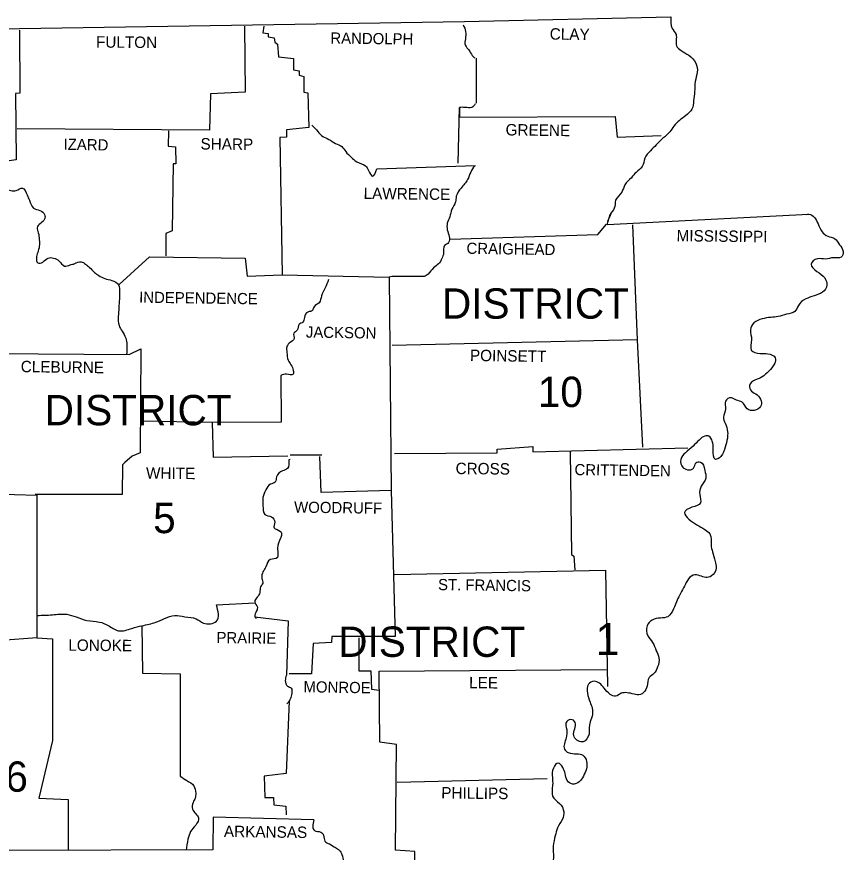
# Model space of a CAD drawing. Extents: x 1370130 to 1380143, y 377636 to 380256.
# Drawn here: x 1379759.2 to 1380085.1, y 379162.8 to 379492.1 of the extents above; entities that cross this region are included whole.
import ezdxf

# ---------------------------------------------------------------- set-up
doc = ezdxf.new("R2010")
doc.units = 0
doc.layers.add('R_Draft', color=7, linetype='Continuous')

msp = doc.modelspace()

# ---------------------------------------------------------------- linework, layer by layer
at = {"layer": 'R_Draft'}
for p, q in [((1379991.99, 379410.22), (1379993.25, 379414.1)), ((1379992.31, 379411.48), (1379993.57, 379414.52)), ((1379866.99, 379319.41), (1379879.47, 379319.41))]:
    msp.add_line(p, q, dxfattribs=at)
for points in [[(1379441.86, 379487.29), (1379611.43, 379487.19), (1379760.24, 379487.5), (1379935.79, 379490.23), (1380017.16, 379492.12)], [(1379760.24, 379486.88), (1379760.45, 379461.92), (1379758.66, 379461.81), (1379758.98, 379435.7), (1379751.64, 379434.65), (1379752.27, 379427.63), (1379754.78, 379424.38), (1379754.57, 379416.09), (1379740.31, 379415.57), (1379739.79, 379402.77), (1379726.78, 379402.35), (1379726.15, 379386.83), (1379726.89, 379385.58), (1379727.2, 379360.83), (1379749.64, 379359.36), (1379749.33, 379304.1), (1379767.16, 379303.57), (1379767.16, 379247.36), (1379753.11, 379246.31), (1379752.06, 379233.94), (1379728.46, 379233.84)], [(1379849.06, 379488.45), (1379849.27, 379462.44), (1379835.64, 379461.71), (1379835.22, 379447.45), (1379759.4, 379447.87)], [(1379856.61, 379488.34), (1379856.3, 379485.83), (1379858.39, 379485.51), (1379858.29, 379484.25), (1379860.7, 379483.73), (1379860.91, 379482.05), (1379862.06, 379481.32), (1379862.38, 379476.28), (1379868.36, 379475.65), (1379868.36, 379471.15), (1379870.56, 379470.83), (1379870.56, 379469.05), (1379872.44, 379468.52), (1379872.34, 379462.44), (1379874.02, 379462.13), (1379874.44, 379448.39), (1379865.52, 379447.55), (1379865.63, 379444.61), (1379862.9, 379444.51), (1379863.85, 379390.4), (1379906.11, 379389.46), (1379906.84, 379305.35), (1379879.26, 379304.62), (1379878.74, 379318.78)], [(1379940.4, 379475.76), (1379940.4, 379458.04)], [(1379933.27, 379434.44), (1379933.79, 379456.36), (1379933.79, 379452.48), (1379995.14, 379452.79), (1379995.98, 379444.61), (1380013.28, 379445.24)], [(1379819.07, 379447.13), (1379818.86, 379441.05), (1379821.79, 379440.84), (1379821.9, 379434.13), (1379820.85, 379434.13), (1379820.43, 379407.7), (1379818.02, 379406.65), (1379818.02, 379397.84)], [(1379901.18, 379432.14), (1379940.08, 379433.5)], [(1379991.99, 379410.22), (1380071.59, 379414.31)], [(1379930.12, 379404.45), (1379988.32, 379406.34), (1379991.78, 379410.32)], [(1380002.06, 379410.11), (1380003.84, 379364.71), (1380005.94, 379322.45)], [(1379799.56, 379386.62), (1379811.52, 379397.43), (1379849.27, 379396.9), (1379850, 379389.88), (1379863.74, 379390.4)], [(1379919.85, 379389.67), (1379907.05, 379389.67), (1379906.11, 379389.46)], [(1380003.84, 379364.71), (1379907.26, 379362.51)], [(1379749.64, 379359.36), (1379803.55, 379359.04), (1379808.16, 379361.25), (1379807.85, 379320.24), (1379804.7, 379318.88), (1379801.87, 379316.47), (1379800.93, 379315.53), (1379800.82, 379303.78), (1379766.53, 379303.78)], [(1379863.32, 379350.76), (1379863.53, 379332.3), (1379836.27, 379332.2), (1379808.27, 379332.72)], [(1379836.27, 379332.2), (1379836.69, 379318.46), (1379866.15, 379318.99)], [(1379908.1, 379320.03), (1379948.58, 379320.24), (1379948.68, 379321.71), (1379962.74, 379322.76), (1379962.74, 379320.56), (1380023.77, 379322.24)], [(1379977.42, 379320.56), (1379977.94, 379280.19), (1379978.89, 379279.56), (1379979.2, 379274.1)], [(1379977.42, 379320.56), (1379977.94, 379280.19), (1379978.89, 379279.56), (1379979.2, 379274.1)], [(1379977.42, 379320.56), (1379977.94, 379280.19), (1379978.89, 379279.56), (1379979.2, 379274.1)], [(1379977.42, 379320.56), (1379977.94, 379280.19), (1379978.89, 379279.56), (1379979.2, 379274.1)], [(1379977.42, 379320.56), (1379977.94, 379280.19), (1379978.89, 379279.56), (1379979.2, 379274.1)], [(1379866.99, 379317.62), (1379866.47, 379317.52)], [(1379906.84, 379305.35), (1379908.41, 379247.89), (1379883.46, 379247.78), (1379883.35, 379245.48), (1379876.12, 379245.06), (1379875.49, 379233.1), (1379866.68, 379233.1)], [(1379908.1, 379272.32), (1379991.37, 379274)], [(1379991.37, 379274), (1379992.2, 379228.07)], [(1379991.37, 379274), (1379992.2, 379228.07)], [(1379991.37, 379274), (1379992.2, 379228.07)], [(1379991.37, 379274), (1379992.2, 379228.07)], [(1379991.37, 379274), (1379992.2, 379228.07)], [(1379991.37, 379274), (1379992.2, 379228.07)], [(1379991.37, 379274), (1379992.2, 379228.07)], [(1379991.37, 379274), (1379992.2, 379228.07)], [(1379837.94, 379260.37), (1379853.15, 379261.1)], [(1379853.15, 379255.65), (1379866.26, 379253.97), (1379865.52, 379232.58)], [(1379808.58, 379252.19), (1379808.79, 379233.42), (1379823.58, 379233.1), (1379823.68, 379192.83)], [(1379767.16, 379247.36), (1379773.24, 379246.94), (1379773.34, 379206.89), (1379767.89, 379184.13), (1379779.53, 379183.61), (1379779.42, 379163.56)], [(1379894.15, 379247.26), (1379894.05, 379234.26), (1379898.87, 379234.26), (1379899.08, 379227.02), (1379902.12, 379226.7)], [(1379908.1, 379141.24), (1379916.28, 379141.76), (1379916.17, 379163.05), (1379908.52, 379163.58), (1379908.94, 379205.21), (1379902.33, 379206.15), (1379902.12, 379234.15), (1379991.57, 379234.78)], [(1379866.68, 379222.51), (1379865.42, 379193.78), (1379856.82, 379192.83), (1379857.03, 379184.34), (1379860.49, 379184.44), (1379860.59, 379181.51), (1379865.31, 379180.98), (1379865.42, 379177.52)], [(1379909.15, 379190.42), (1379968.29, 379191.89)], [(1379876.33, 379175.64), (1379836.69, 379176.68), (1379836.48, 379163.79), (1379756.25, 379163.47)]]:
    msp.add_lwpolyline(points, dxfattribs=at)
for points in [[(1380017.16, 379492.12), (1380017.69, 379487.5), (1380019.16, 379485.09), (1380019.36, 379480.69), (1380021.15, 379478.8), (1380024.19, 379476.91), (1380026.92, 379473.87), (1380027.54, 379470.31), (1380026.71, 379466.64), (1380026.5, 379462.55), (1380026.08, 379458.98), (1380025.45, 379455.73), (1380022.93, 379453.11), (1380020.52, 379451.22), (1380018.32, 379449.02), (1380016.74, 379446.71), (1380014.02, 379444.2), (1380011.29, 379441.57), (1380009.09, 379439.27), (1380006.89, 379436.33), (1380005.84, 379433.08), (1380003.42, 379430.77), (1380001.54, 379428.68), (1379999.02, 379425.84), (1379997.76, 379423.01), (1379995.35, 379419.76), (1379994.83, 379416.62), (1379993.25, 379414.1), (1379993.15, 379413.68)], [(1379935.26, 379488.87), (1379936.2, 379486.25), (1379936.1, 379483.41), (1379936.1, 379480.79), (1379937.46, 379479.01), (1379938.83, 379476.81), (1379939.87, 379475.86)], [(1379939.98, 379457.72), (1379938.62, 379456.36), (1379935.99, 379456.36), (1379933.79, 379456.36)], [(1379875.59, 379449.33), (1379877.9, 379446.92), (1379879.89, 379444.93), (1379882.2, 379443.78), (1379884.92, 379442.2), (1379887.34, 379440.94), (1379888.91, 379438.95), (1379891.11, 379436.75), (1379893.31, 379434.97), (1379896.77, 379433.29), (1379897.93, 379431.51), (1379899.5, 379429.3), (1379901.18, 379432.14)], [(1379939.77, 379433.39), (1379938.2, 379430.88), (1379936.94, 379427.94), (1379934.42, 379424.59), (1379932.53, 379421.33), (1379932.22, 379419.13), (1379930.75, 379416.2), (1379929.91, 379413.26), (1379928.97, 379410.74), (1379928.97, 379408.12), (1379929.7, 379405.5), (1379929.49, 379403.09), (1379927.92, 379401.93), (1379927.5, 379398.89), (1379926.87, 379396.8), (1379925.51, 379394.7), (1379923.52, 379393.13), (1379921.42, 379390.71), (1379919.85, 379389.67)], [(1379754.78, 379424.38), (1379758.98, 379423.64), (1379761.49, 379424.59), (1379763.28, 379421.86), (1379764.22, 379419.76), (1379765.79, 379416.72), (1379768.31, 379415.78), (1379770.2, 379414.1), (1379770.2, 379412.32), (1379768.52, 379410.64), (1379767.26, 379408.96), (1379767.68, 379406.97), (1379768.1, 379404.24), (1379768.1, 379401.62), (1379767.47, 379399.21), (1379766.95, 379397.01), (1379767.47, 379395.12), (1379769.46, 379395.43), (1379771.56, 379397.01), (1379773.76, 379397.01), (1379775.86, 379395.85), (1379778.06, 379393.86), (1379780.27, 379394.28), (1379782.05, 379394.8), (1379784.57, 379395.54), (1379786.35, 379394.59), (1379787.92, 379393.34), (1379789.81, 379391.34), (1379791.59, 379390.08), (1379793.9, 379388.93), (1379796.73, 379388.2), (1379799.35, 379386.41), (1379799.77, 379383.37), (1379799.67, 379380.75), (1379799.46, 379377.5), (1379799.25, 379373.94), (1379799.56, 379370.47), (1379800.72, 379368.17), (1379802.18, 379365.44), (1379802.6, 379362.92), (1379802.5, 379358.94)], [(1380070.44, 379414.2), (1380071.59, 379414.31), (1380075.15, 379410.53), (1380076.73, 379407.39), (1380079.03, 379405.6), (1380081.66, 379404.66), (1380083.65, 379402.25), (1380085.01, 379399.63), (1380084.28, 379397.32), (1380081.34, 379397.11), (1380078.09, 379396.59), (1380074.94, 379396.69), (1380072.43, 379394.59), (1380074.74, 379391.76), (1380077.78, 379389.14), (1380078.62, 379386.31), (1380076.94, 379383.58), (1380073.58, 379382.12), (1380070.33, 379380.86), (1380067.39, 379378.34), (1380066.03, 379375.93), (1380062.78, 379374.88), (1380059.42, 379373.94), (1380056.49, 379373.62), (1380053.13, 379372.99), (1380049.88, 379371.42), (1380048.52, 379368.69), (1380048.94, 379364.81), (1380048.83, 379360.72), (1380052.29, 379359.36), (1380055.33, 379359.25), (1380058.27, 379357.68), (1380057.96, 379355.37), (1380055.75, 379352.44), (1380053.13, 379350.13), (1380050.51, 379348.98), (1380048.1, 379346.78), (1380048.94, 379344.57), (1380051.14, 379343.11), (1380052.71, 379340.69), (1380052.5, 379338.49), (1380049.99, 379336.92), (1380047.26, 379337.55), (1380045.27, 379340.17), (1380042.96, 379341.01), (1380040.97, 379341.95), (1380038.66, 379340.59), (1380038.66, 379337.55), (1380037.82, 379334.3), (1380038.56, 379331.88), (1380039.5, 379328.53), (1380039.39, 379326.01), (1380038.56, 379322.45), (1380036.77, 379318.78), (1380034.68, 379317.62), (1380033.84, 379321.61), (1380033.42, 379324.86), (1380032.16, 379326.75), (1380030.48, 379326.85), (1380028.28, 379325.28), (1380025.87, 379322.87), (1380022.83, 379320.24), (1380021.04, 379317.62), (1380021.99, 379314.37), (1380024.29, 379313.53), (1380026.08, 379314.16), (1380027.02, 379316.26), (1380028.8, 379316.57), (1380030.48, 379313.32)], [(1379882.09, 379388.51), (1379880.83, 379385.26), (1379879.37, 379382.12), (1379878.42, 379379.39), (1379876.43, 379377.82), (1379875.8, 379376.35), (1379874.02, 379375.72), (1379872.65, 379373.62), (1379872.03, 379371.73), (1379870.56, 379370.89), (1379869.82, 379368.59), (1379868.46, 379367.33), (1379868.56, 379365.23), (1379866.99, 379363.76), (1379865.73, 379362.09), (1379865.73, 379359.78), (1379866.26, 379356.74), (1379867.31, 379354.95), (1379868.25, 379352.65), (1379868.15, 379351.18), (1379865.52, 379351.18), (1379863.32, 379350.76)], [(1379866.47, 379317.52), (1379865.94, 379314.06), (1379863.95, 379313.11), (1379861.64, 379310.81), (1379861.12, 379308.71), (1379859.23, 379307.87), (1379857.45, 379305.67), (1379856.3, 379302.63), (1379856.3, 379299.48), (1379857.03, 379295.92), (1379859.65, 379294.97), (1379860.91, 379292.87), (1379860.7, 379290.67), (1379863.22, 379289.2), (1379863.64, 379287.95), (1379863.22, 379286.58), (1379862.06, 379282.7), (1379862.17, 379280.08), (1379861.96, 379278.93), (1379859.13, 379278.19), (1379857.45, 379275.36), (1379856.3, 379273.37), (1379855.88, 379270.75), (1379856.19, 379268.86), (1379855.35, 379267.39), (1379855.04, 379265.19), (1379853.99, 379263.3), (1379853.04, 379261.52), (1379854.09, 379259.42), (1379853.78, 379257.95), (1379853.15, 379255.65), (1379853.67, 379254.91)], [(1380030.48, 379313.32), (1380030.9, 379310.28), (1380029.12, 379307.03), (1380028.49, 379303.78), (1380028.8, 379300.53), (1380025.45, 379298.75), (1380022.51, 379296.65), (1380024.19, 379294.13), (1380027.33, 379291.83), (1380030.48, 379290.04), (1380032.47, 379288.26), (1380033, 379283.96), (1380033.52, 379281.23), (1380034.57, 379277.46), (1380034.99, 379274.84), (1380033.1, 379271.69), (1380030.9, 379271.06), (1380028.59, 379271.8), (1380025.87, 379272.01), (1380023.66, 379269.91), (1380022.09, 379266.97), (1380020.52, 379264.04), (1380019.36, 379261.52), (1380018.21, 379258.79), (1380015.9, 379255.65), (1380013.07, 379255.12), (1380009.72, 379254.28), (1380007.72, 379251.98), (1380008.04, 379248.1), (1380009.93, 379245.48), (1380011.39, 379242.22), (1380012.44, 379239.39), (1380011.92, 379235.83), (1380010.45, 379233.21), (1380008.56, 379231.63), (1380007.72, 379228.28), (1380006.36, 379225.76), (1380005.1, 379224.92), (1380002.59, 379225.13), (1379999.86, 379225.66), (1379997.55, 379225.45), (1379995.35, 379224.29), (1379993.15, 379225.03), (1379990.84, 379227.54), (1379988.95, 379229.43), (1379986.86, 379230.17), (1379984.65, 379229.01), (1379984.23, 379225.55), (1379985.28, 379221.99), (1379986.23, 379217.16), (1379985.28, 379214.23), (1379984.97, 379209.4)], [(1379767.37, 379256.17), (1379773.24, 379256.38), (1379779.01, 379256.59), (1379782.68, 379255.54), (1379786.87, 379254.18), (1379791.8, 379253.55), (1379795.26, 379252.19), (1379799.35, 379250.09), (1379804.6, 379251.03), (1379808.69, 379252.08), (1379814.03, 379253.45), (1379817.49, 379254.91), (1379821.48, 379256.17), (1379825.46, 379255.65), (1379829.97, 379254.81), (1379832.8, 379253.13), (1379837.94, 379253.86), (1379837.94, 379260.37)], [(1379865.52, 379232.58), (1379865.1, 379230.48), (1379865.94, 379228.28), (1379867.41, 379227.54), (1379867.62, 379225.45), (1379867.1, 379223.35), (1379866.68, 379222.51), (1379865.73, 379221.25)], [(1379984.97, 379209.4), (1379982.56, 379206.36), (1379978.99, 379208.25), (1379978.99, 379210.77), (1379979.52, 379213.39), (1379978.26, 379215.06), (1379976.05, 379214.33), (1379976.05, 379211.08), (1379975.84, 379207.93), (1379975.22, 379203.42), (1379976.68, 379202.06), (1379980.04, 379201.64), (1379982.45, 379201.01), (1379983.92, 379198.6), (1379983.81, 379195.66), (1379982.66, 379192.83), (1379980.98, 379190.53), (1379978.36, 379189.69), (1379976.26, 379191.05), (1379975.43, 379193.78), (1379974.48, 379196.19), (1379972.7, 379197.97), (1379970.81, 379195.98), (1379970.39, 379192.31), (1379970.5, 379189.16), (1379970.5, 379184.86), (1379973.22, 379182.03), (1379974.9, 379178.78), (1379974.38, 379175.85), (1379972.38, 379172.38), (1379971.55, 379169.34), (1379970.71, 379165.25), (1379970.81, 379160.74), (1379970.08, 379156.34), (1379968.61, 379153.4), (1379965.88, 379150.99), (1379964.1, 379149.42), (1379962.63, 379147.85), (1379961.9, 379144.7), (1379961.37, 379142.5), (1379959.38, 379139.88), (1379957.81, 379139.67), (1379956.55, 379140.72), (1379956.13, 379142.5), (1379956.13, 379144.28), (1379955.29, 379146.06), (1379952.67, 379146.8), (1379950.57, 379146.69), (1379949.63, 379145.22), (1379950.99, 379141.13), (1379951.52, 379138.51), (1379950.78, 379134.95), (1379951.2, 379134.53), (1379947.43, 379132.54), (1379944.38, 379132.22), (1379941.87, 379131.49), (1379939.46, 379129.91), (1379938.3, 379127.61), (1379936.62, 379125.72), (1379935.16, 379123.94), (1379933.16, 379123.1), (1379930.96, 379123.52), (1379928.02, 379123.83), (1379926.35, 379121.73), (1379926.87, 379118.69), (1379928.86, 379116.91), (1379931.8, 379116.07), (1379934.84, 379116.28), (1379937.78, 379116.6), (1379940.5, 379115.13), (1379939.98, 379112.3), (1379937.36, 379110.93), (1379933.48, 379110.51), (1379930.33, 379110.83), (1379926.56, 379109.99), (1379924.67, 379107.58), (1379925.72, 379103.91), (1379929.81, 379102.44), (1379931.7, 379098.98), (1379931.8, 379095.73), (1379930.44, 379091.43), (1379928.55, 379089.44), (1379924.88, 379088.6), (1379922.05, 379088.07), (1379921.63, 379083.25), (1379920.37, 379080.84), (1379918.17, 379080.1), (1379915.02, 379081.68), (1379913.13, 379082.41), (1379910.83, 379083.46), (1379907.89, 379085.24), (1379905.69, 379084.93), (1379906.32, 379080.31), (1379906.53, 379080.1), (1379909.04, 379076.64), (1379911.56, 379073.92), (1379912.71, 379070.67)], [(1379823.68, 379192.83), (1379826.3, 379191.05), (1379829.03, 379188.95), (1379829.76, 379186.12), (1379829.55, 379184.13), (1379828.72, 379182.45), (1379828.51, 379179.83), (1379829.76, 379177.94), (1379830.92, 379176.37), (1379829.76, 379173.54), (1379827.77, 379170.92), (1379826.72, 379167.98), (1379825.99, 379163.58)], [(1379876.33, 379175.64), (1379876.64, 379171.34), (1379879.16, 379170.71), (1379880.21, 379169.55), (1379880.73, 379167.14), (1379882.51, 379166.09), (1379884.92, 379164.62), (1379886.39, 379163.58), (1379887.44, 379161.9), (1379888.07, 379159.17), (1379889.75, 379157.39), (1379892.06, 379156.55), (1379893.73, 379154.56), (1379894.78, 379151.73), (1379896.46, 379150.47), (1379898.14, 379148.27), (1379898.98, 379147.32), (1379900.44, 379144.8), (1379901.91, 379143.55), (1379902.96, 379142.81), (1379904.64, 379142.29), (1379906.74, 379140.92), (1379908.1, 379138.83), (1379908.1, 379137.25), (1379907.58, 379134.84), (1379907.16, 379132.33), (1379906.95, 379129.49), (1379906.74, 379126.98), (1379907.68, 379124.88), (1379907.16, 379121.73), (1379906.11, 379120.06), (1379906, 379117.75), (1379905.69, 379114.29), (1379905.27, 379112.3), (1379904.32, 379109.05), (1379902.96, 379107.37)]]:
    msp.add_spline(points, degree=3, dxfattribs=at)

# ---------------------------------------------------------------- texts
for s, height, rotation, p in [('CLAY', 4.509, 359.2258, (1379969.34, 379483.1)), ('FULTON', 4.509, 359.4996, (1379790.44, 379479.95)), ('RANDOLPH', 4.405, 359.2584, (1379882.83, 379481.53)), ('GREENE', 4.51, 359.2361, (1379951.93, 379445.35)), ('IZARD', 4.404, 358.9259, (1379777.64, 379439.69)), ('SHARP', 4.509, 359.3905, (1379831.65, 379439.79)), ('LAWRENCE', 4.51, 359.2678, (1379895.94, 379420.29)), ('MISSISSIPPI', 4.5087, 359.3097, (1380019.36, 379403.61)), ('CRAIGHEAD', 4.405, 359.1159, (1379936.52, 379398.68)), ('INDEPENDENCE', 4.4036, 359.2188, (1379807.43, 379379.39)), ('JACKSON', 4.404, 359.1352, (1379873.18, 379365.65)), ('POINSETT', 4.509, 359.1987, (1379937.88, 379356.42)), ('CLEBURNE', 4.509, 359.2535, (1379760.76, 379352.02)), ('CROSS', 4.509, 359.384, (1379932.22, 379311.86)), ('CRITTENDEN', 4.405, 359.213, (1379979.1, 379311.44)), ('WHITE', 4.51, 359.3139, (1379810.15, 379310.07)), ('WOODRUFF', 4.404, 359.2748, (1379868.56, 379296.65)), ('ST. FRANCIS', 4.4036, 359.2216, (1379925.3, 379266.13)), ('PRAIRIE', 4.405, 359.2116, (1379837.94, 379245.27)), ('LONOKE', 4.51, 359.4974, (1379779.53, 379242.22)), ('MONROE', 4.404, 359.0331, (1379872.24, 379225.87)), ('LEE', 4.51, 359.4327, (1379937.57, 379227.44)), ('PHILLIPS', 4.509, 359.318, (1379926.56, 379184.02)), ('ARKANSAS', 4.509, 359.2678, (1379840.88, 379168.82))]:
    msp.add_text(s, height=height, rotation=rotation, dxfattribs=at).set_placement(p)
for s, height, p in [('DISTRICT', 11.955, (1379926.87, 379373.1)), ('10', 11.955, (1379964.65, 379338.28)), ('DISTRICT', 11.955, (1379770.21, 379331.09)), ('5', 11.95, (1379812.98, 379288.58)), ('1', 12.58, (1379987.49, 379240.55)), ('DISTRICT', 11.955, (1379885.97, 379239.81)), ('DISTRICT 6', 11.955, (1379676.55, 379186.65))]:
    msp.add_text(s, height=height, dxfattribs=at).set_placement(p)

doc.saveas('drawing.dxf')
